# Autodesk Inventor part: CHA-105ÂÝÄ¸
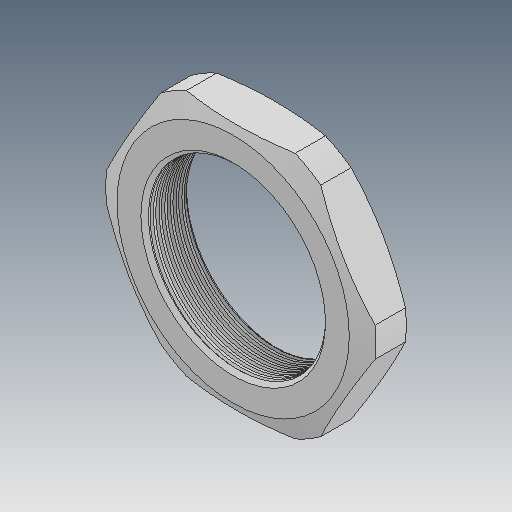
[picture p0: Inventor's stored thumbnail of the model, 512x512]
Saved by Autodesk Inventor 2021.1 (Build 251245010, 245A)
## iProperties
Created: 2019-05
Part Number: CHA-105ÂÝÄ¸
Material: Ogólny
Document SubType Name: Modeling
Designer: user
Density: 1 g/cm^3
Appearance: Domyślna
Author: user
Revision Number: ÈÎºÎ
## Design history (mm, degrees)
feature "¾µÏò1"
node "Bryła1"
